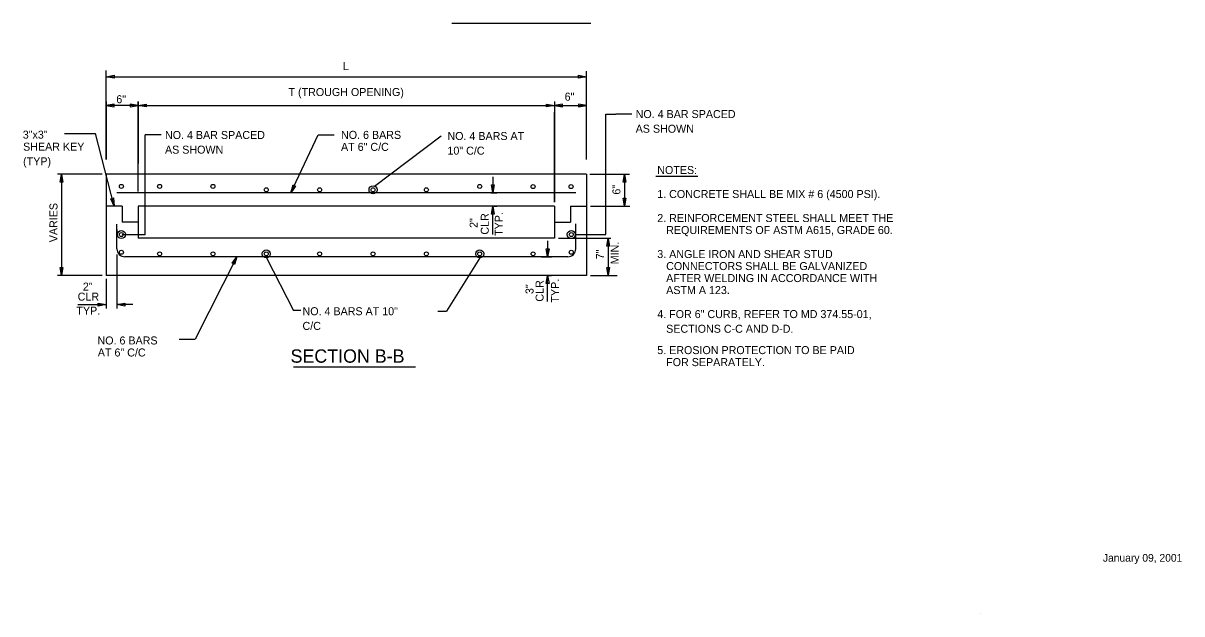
# Model space of a CAD drawing. Extents: x 12.4 to 21.1, y 6 to 16.1.
# Drawn here: x 12.44 to 21.13, y 5.98 to 10.41 of the extents above; entities that cross this region are included whole.
import ezdxf

# ---------------------------------------------------------------- set-up
doc = ezdxf.new("R2010")
doc.units = 0
for name, color, linetype in [('DETL-NOTE', 7, 'Continuous'), ('TTLB-TEXT', 7, 'Continuous'), ('V7_LEVEL_1', 7, 'Continuous'), ('V7_LEVEL_10', 7, 'Continuous'), ('V7_LEVEL_12', 7, 'Continuous'), ('V7_LEVEL_13', 7, 'Continuous'), ('V7_LEVEL_44', 7, 'Continuous')]:
    doc.layers.add(name, color=color, linetype=linetype)

msp = doc.modelspace()

# ---------------------------------------------------------------- linework, layer by layer
at = {"layer": 'TTLB-TEXT'}
msp.add_line((19.6208, 5.9844), (19.6208, 5.9844), dxfattribs=at)
at = {"layer": 'V7_LEVEL_1'}
for p, q in [((13.0647, 9.2809), (13.0647, 8.5209)), ((14.8647, 9.2809), (13.0647, 9.2809)), ((16.6647, 9.2809), (14.8647, 9.2809)), ((16.6647, 9.2809), (16.6647, 8.5209)), ((16.5847, 9.1409), (13.1447, 9.1409)), ((13.1847, 9.0409), (13.0647, 9.0409)), ((13.1847, 9.0409), (13.1847, 8.9209)), ((14.8647, 9.0409), (13.3047, 9.0409)), ((13.3047, 9.0409), (13.3047, 8.914)), ((16.4247, 9.0409), (14.8647, 9.0409)), ((16.4247, 9.0409), (16.4247, 8.8009)), ((16.5447, 9.0409), (16.5447, 8.9209)), ((16.5447, 9.0409), (16.6647, 9.0409)), ((16.5447, 9.0409), (16.5447, 8.9209)), ((13.1447, 8.7209), (13.1447, 8.9053)), ((13.3047, 8.9209), (13.1847, 8.9209)), ((13.3047, 8.9209), (13.3047, 8.8009)), ((16.4247, 8.9209), (16.5447, 8.9209)), ((16.5847, 8.7209), (16.5847, 8.9077)), ((14.8647, 8.8009), (13.3047, 8.8009)), ((16.4247, 8.8009), (14.8647, 8.8009)), ((14.8647, 8.6609), (13.2047, 8.6609)), ((16.5247, 8.6609), (14.8647, 8.6609)), ((14.8647, 8.5209), (13.0647, 8.5209)), ((16.6647, 8.5209), (14.8647, 8.5209))]:
    msp.add_line(p, q, dxfattribs=at)
for centre in [(13.1781, 9.1886), (13.4647, 9.1886), (13.8647, 9.1886), (14.2647, 9.1628), (14.6647, 9.1628), (15.0647, 9.1628), (15.4647, 9.1628), (15.8647, 9.1881), (16.2647, 9.187), (16.5492, 9.187), (13.1781, 8.8278), (16.5512, 8.8278), (13.1781, 8.6948), (13.4647, 8.6828), (13.8647, 8.6828), (14.2647, 8.6828), (14.6647, 8.6828), (15.0647, 8.6828), (15.4647, 8.6828), (15.8647, 8.6828), (16.2647, 8.6828), (16.5512, 8.6948)]:
    msp.add_circle(centre, 0.015, dxfattribs=at)
for centre, start, end in [((13.2047, 8.7209), 180.00002, 270.00002), ((16.5247, 8.7209), 269.99998, 0.00002)]:
    msp.add_arc(centre, 0.06, start, end, dxfattribs=at)
at = {"layer": 'V7_LEVEL_10'}
for p, q in [((13.0647, 9.3909), (13.0647, 10.0571)), ((13.0647, 10.0108), (14.5952, 10.0108)), ((14.5952, 10.0108), (16.6647, 10.0108)), ((16.6647, 9.3909), (16.6647, 10.0513)), ((13.0647, 9.8253), (13.0647, 9.3909)), ((13.3047, 9.1509), (13.3047, 9.8253)), ((13.3047, 9.8253), (13.3047, 9.3596)), ((16.4247, 9.8253), (16.4247, 9.0709)), ((16.6647, 9.3909), (16.6647, 9.8253)), ((13.1247, 9.8058), (13.0647, 9.7953)), ((13.3047, 9.7953), (13.0647, 9.7953)), ((13.0647, 9.7953), (13.1247, 9.7848)), ((13.1247, 9.7848), (13.1247, 9.8058)), ((13.3047, 9.7953), (13.2447, 9.8058)), ((13.2447, 9.8058), (13.2447, 9.7848)), ((13.2447, 9.7848), (13.3047, 9.7953)), ((13.3047, 9.7953), (14.5892, 9.7953)), ((14.5892, 9.7953), (16.4247, 9.7953)), ((16.4847, 9.8058), (16.4247, 9.7953)), ((16.4247, 9.7953), (16.6647, 9.7953)), ((16.4247, 9.7953), (16.4847, 9.7848)), ((16.4247, 9.0709), (16.4247, 9.7453)), ((16.4847, 9.7848), (16.4847, 9.8058)), ((16.6647, 9.7953), (16.6047, 9.8058)), ((16.6047, 9.8058), (16.6047, 9.7848)), ((16.6047, 9.7848), (16.6647, 9.7953)), ((16.8105, 8.8278), (16.8105, 9.7308)), ((16.8105, 9.7308), (16.884, 9.7308)), ((17.004, 9.7308), (16.884, 9.7308)), ((12.752, 9.586), (12.9848, 9.586)), ((13.1247, 9.0409), (12.9848, 9.586)), ((13.4755, 9.574), (13.3555, 9.574)), ((13.3555, 8.8278), (13.3555, 9.574)), ((14.4493, 9.1409), (14.6523, 9.574)), ((14.6523, 9.574), (14.7723, 9.574)), ((15.0766, 9.1903), (15.5754, 9.5664)), ((13.0347, 9.2809), (12.6995, 9.2809)), ((12.7295, 9.2809), (12.7295, 8.5209)), ((15.9625, 9.2609), (15.9625, 9.1409)), ((16.691, 9.2809), (16.9882, 9.2809)), ((16.9497, 9.2809), (16.9497, 9.0409)), ((15.9501, 9.1409), (15.9925, 9.1409)), ((15.9625, 8.8269), (15.9625, 9.0409)), ((15.9739, 9.0409), (15.9925, 9.0409)), ((16.6946, 9.0409), (16.9889, 9.0409)), ((13.1447, 8.865), (13.1447, 8.8226)), ((13.1847, 8.8278), (13.3555, 8.8278)), ((16.3736, 8.7809), (16.3736, 8.6609)), ((16.4546, 8.8009), (16.848, 8.8009)), ((16.5812, 8.8278), (16.8105, 8.8278)), ((16.8271, 8.8009), (16.8271, 8.5209)), ((13.1447, 8.679), (13.1447, 8.2721)), ((14.0449, 8.6609), (13.732, 8.0431)), ((14.2673, 8.6529), (14.4677, 8.2571)), ((15.8647, 8.6528), (15.6154, 8.2528)), ((16.3253, 8.6609), (16.4036, 8.6609)), ((13.0347, 8.5209), (12.6995, 8.5209)), ((16.3736, 8.3248), (16.3736, 8.5209)), ((16.3791, 8.5209), (16.4036, 8.5209)), ((16.6946, 8.5209), (16.848, 8.5209)), ((16.6947, 8.5209), (16.8957, 8.5209)), ((13.0647, 8.4958), (13.0647, 8.2721)), ((12.8507, 8.3021), (13.0647, 8.3021)), ((13.2647, 8.3021), (13.1447, 8.3021)), ((14.5247, 8.2571), (14.4677, 8.2571)), ((15.5517, 8.2528), (15.6154, 8.2528)), ((13.612, 8.0431), (13.732, 8.0431))]:
    msp.add_line(p, q, dxfattribs=at)
for points in [[(13.1247, 10.0003), (13.0647, 10.0108), (13.1247, 10.0213)], [(16.6047, 10.0213), (16.6647, 10.0108), (16.6047, 10.0003)], [(13.3647, 9.7848), (13.3047, 9.7953), (13.3647, 9.8058)], [(16.3647, 9.8058), (16.4247, 9.7953), (16.3647, 9.7848)], [(12.719, 9.2209), (12.7295, 9.2809), (12.74, 9.2209)], [(16.9392, 9.2209), (16.9497, 9.2809), (16.9602, 9.2209)], [(14.4842, 9.1907), (14.4493, 9.1409), (14.4652, 9.1997)], [(15.973, 9.2009), (15.9625, 9.1409), (15.952, 9.2009)], [(13.1199, 9.1016), (13.1247, 9.0409), (13.0996, 9.0964)], [(15.952, 8.9809), (15.9625, 9.0409), (15.973, 8.9809)], [(16.9602, 9.1009), (16.9497, 9.0409), (16.9392, 9.1009)], [(16.8166, 8.7409), (16.8271, 8.8009), (16.8376, 8.7409)], [(16.3841, 8.7209), (16.3736, 8.6609), (16.3631, 8.7209)], [(14.0084, 8.6121), (14.0449, 8.6609), (14.0271, 8.6026)], [(12.74, 8.5809), (12.7295, 8.5209), (12.719, 8.5809)], [(16.3631, 8.4609), (16.3736, 8.5209), (16.3841, 8.4609)], [(16.8376, 8.5809), (16.8271, 8.5209), (16.8166, 8.5809)], [(13.0047, 8.3126), (13.0647, 8.3021), (13.0047, 8.2916)], [(13.2047, 8.2916), (13.1447, 8.3021), (13.2047, 8.3126)]]:
    msp.add_lwpolyline(points, close=True, dxfattribs=at)
for centre in [(15.0647, 9.1628), (13.1781, 8.8278), (16.5512, 8.8278), (14.2647, 8.6828), (15.8647, 8.6828)]:
    msp.add_circle(centre, 0.03, dxfattribs=at)
at = {"layer": 'V7_LEVEL_13'}
msp.add_line((17.1854, 9.2643), (17.5003, 9.2643), dxfattribs=at)
at = {"layer": 'V7_LEVEL_44'}
for p, q in [((15.6544, 10.412), (16.6981, 10.412)), ((14.4693, 7.8359), (15.382, 7.8359))]:
    msp.add_line(p, q, dxfattribs=at)

# ---------------------------------------------------------------- texts
at = {"layer": 'DETL-NOTE'}
msp.add_text('January 09, 2001', height=0.0576, dxfattribs=at).set_placement((20.5367, 6.3752))
at = {"layer": 'V7_LEVEL_12'}
for s, height, p in [('L', 0.06, (14.839, 10.0604)), ('T (TROUGH OPENING)', 0.06, (14.4313, 9.8657)), ('6"', 0.06, (13.1403, 9.8119)), ('6"', 0.06, (16.5013, 9.831)), ('NO. 4 BAR SPACED', 0.06, (17.0338, 9.7007)), ('AS SHOWN', 0.06, (17.0338, 9.5907)), ('3"x3"', 0.06, (12.439, 9.5464)), ('NO. 4 BAR SPACED', 0.06, (13.5053, 9.5438)), ('NO. 6 BARS', 0.06, (14.825, 9.5447)), ('NO. 4 BARS AT', 0.06, (15.6227, 9.5364)), ('SHEAR KEY', 0.06, (12.4415, 9.4564)), ('AS SHOWN', 0.06, (13.5053, 9.4338)), ('AT 6" C/C', 0.06, (14.825, 9.4547)), ('10" C/C', 0.06, (15.6227, 9.4264)), ('(TYP)', 0.06, (12.4415, 9.3464)), ('2"', 0.06, (12.8895, 8.4075)), ('CLR', 0.06, (12.8505, 8.332)), ('TYP.', 0.06, (12.841, 8.227)), ('NO. 4 BARS AT 10"', 0.06, (14.5362, 8.2227)), ('C/C', 0.06, (14.5362, 8.1127)), ('NO. 6 BARS ', 0.06, (12.9991, 8.0035)), ('AT 6" C/C', 0.06, (13.0016, 7.9135)), ('SECTION B-B', 0.1, (14.4466, 7.8668))]:
    msp.add_text(s, height=height, dxfattribs=at).set_placement(p)
for s, p in [('6"', (16.9195, 9.1269)), ('VARIES', (12.6993, 8.7699)), ('CLR', (15.9323, 8.8269)), ('TYP.', (16.0375, 8.8172)), ('2"', (15.8495, 8.8769)), ('7"', (16.797, 8.6419)), ('MIN.', (16.907, 8.6047)), ('3"', (16.268, 8.3814)), ('CLR', (16.3435, 8.3247)), ('TYP.', (16.459, 8.3174))]:
    msp.add_text(s, height=0.06, rotation=90, dxfattribs=at).set_placement(p)
at = {"layer": 'V7_LEVEL_13'}
for s, p in [('NOTES:', (17.1956, 9.2813)), ('1. CONCRETE SHALL BE MIX # 6 (4500 PSI).', (17.1956, 9.1013)), ('2. REINFORCEMENT STEEL SHALL MEET THE', (17.1956, 8.9213)), ('   REQUIREMENTS OF ASTM A615, GRADE 60.', (17.1956, 8.8313)), ('3. ANGLE IRON AND SHEAR STUD', (17.1956, 8.6513)), ('   CONNECTORS SHALL BE GALVANIZED', (17.1956, 8.5613)), ('   AFTER WELDING IN ACCORDANCE WITH', (17.1956, 8.4713)), ('   ASTM A 123. ', (17.1956, 8.3813)), ('4. FOR 6" CURB, REFER TO MD 374.55-01, ', (17.1956, 8.2013)), ('   SECTIONS C-C AND D-D.', (17.1956, 8.0913)), ('5. EROSION PROTECTION TO BE PAID', (17.1956, 7.9313)), ('   FOR SEPARATELY.', (17.1956, 7.8413))]:
    msp.add_text(s, height=0.06, dxfattribs=at).set_placement(p)

doc.saveas('drawing.dxf')
